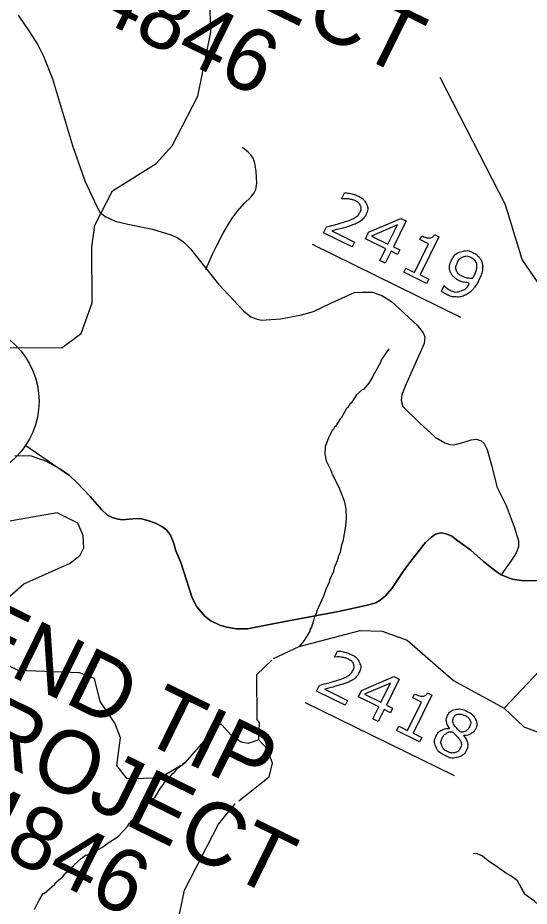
# Model space of a CAD drawing. Extents: x 1428428 to 1430511, y 857911 to 859585.
# Drawn here: x 1429106.2 to 1429187.5, y 859309.5 to 859450.7 of the extents above; entities that cross this region are included whole.
import ezdxf

# ---------------------------------------------------------------- set-up
doc = ezdxf.new("R2010")
doc.units = 0
for name, color, linetype in [('Default', 7, 'Continuous'), ('Exist Hydrographic Creek Single Shore', 7, 'Continuous'), ('Exist Hydrographic Misc Water Feature', 7, 'Continuous'), ('Exist Road Non-System Type 51', 7, 'Continuous'), ('Exist Road Secondary Type 51 Attributed', 7, 'Continuous'), ('Sheet Title CELL', 7, 'Continuous')]:
    doc.layers.add(name, color=color, linetype=linetype)

msp = doc.modelspace()

# ---------------------------------------------------------------- linework, layer by layer
at = {"layer": 'Default'}
for p, q in [((1429153.04, 859414.68), (1429176.61, 859403.09)), ((1429151.93, 859341.85), (1429175.56, 859330.22))]:
    msp.add_line(p, q, dxfattribs=at)
for points in [[(1429157.75, 859421.88), (1429157.7, 859421.9), (1429158.17, 859422.85)], [(1429159.39, 859414.24), (1429154.83, 859416.48), (1429155.3, 859417.43)], [(1429166.57, 859413.05), (1429165.57, 859413.55), (1429164.64, 859411.65), (1429163.77, 859412.08), (1429164.71, 859413.97), (1429161.48, 859415.56), (1429161.99, 859416.6), (1429167.12, 859418.79), (1429167.95, 859418.38), (1429165.93, 859414.27), (1429166.93, 859413.78), (1429166.57, 859413.05)], [(1429165.06, 859414.7), (1429166.56, 859417.74), (1429162.45, 859415.98), (1429165.06, 859414.7)], [(1429156.15, 859416.8), (1429159.77, 859415.02), (1429159.39, 859414.24)], [(1429171.2, 859408.42), (1429167.56, 859410.22), (1429167.9, 859410.9), (1429169.3, 859410.21), (1429171.52, 859414.72), (1429170.12, 859415.41), (1429170.42, 859416.03)], [(1429172.45, 859416.2), (1429173.15, 859415.85), (1429170.17, 859409.79), (1429171.54, 859409.11), (1429171.2, 859408.42)], [(1429173.55, 859407.23), (1429173.98, 859408.1), (1429174.02, 859408.08)], [(1429156.63, 859349.05), (1429156.58, 859349.07), (1429157.05, 859350.02)], [(1429165.46, 859340.22), (1429164.46, 859340.71), (1429163.52, 859338.82), (1429162.66, 859339.24), (1429163.59, 859341.14), (1429160.36, 859342.73), (1429160.87, 859343.77), (1429166, 859345.96), (1429166.83, 859345.55), (1429164.81, 859341.44), (1429165.81, 859340.95), (1429165.46, 859340.22)], [(1429158.27, 859341.4), (1429153.71, 859343.65), (1429154.18, 859344.6)], [(1429155.03, 859343.97), (1429158.65, 859342.18), (1429158.27, 859341.4)], [(1429163.94, 859341.87), (1429165.44, 859344.9), (1429161.33, 859343.15), (1429163.94, 859341.87)], [(1429170.08, 859335.59), (1429166.44, 859337.38), (1429166.78, 859338.07), (1429168.18, 859337.38), (1429170.4, 859341.89), (1429169, 859342.58), (1429169.3, 859343.19)], [(1429171.33, 859343.36), (1429172.03, 859343.02), (1429169.05, 859336.95), (1429170.42, 859336.28), (1429170.08, 859335.59)], [(1429174.84, 859337.71), (1429174.86, 859337.74)], [(1429177.08, 859336.6), (1429177.06, 859336.57)]]:
    msp.add_lwpolyline(points, dxfattribs=at)
for points in [[(1429155.3, 859417.43), (1429155.97, 859417.6), (1429156.65, 859417.78), (1429157.33, 859417.95), (1429157.94, 859418.15), (1429159.22, 859418.56), (1429159.79, 859418.89), (1429160.35, 859419.23), (1429160.63, 859419.8), (1429160.89, 859420.33), (1429160.69, 859420.79), (1429160.49, 859421.26), (1429159.87, 859421.57), (1429159.46, 859421.77), (1429158.9, 859421.86), (1429158.35, 859421.95), (1429157.75, 859421.88)], [(1429158.17, 859422.85), (1429158.57, 859422.85), (1429159.17, 859422.72), (1429159.77, 859422.58), (1429160.27, 859422.34), (1429161.31, 859421.83), (1429161.65, 859421.04), (1429161.99, 859420.25), (1429161.57, 859419.4), (1429161.38, 859419.01), (1429161.12, 859418.73), (1429160.86, 859418.45), (1429160.53, 859418.24), (1429160.21, 859418.05), (1429159.84, 859417.89), (1429159.47, 859417.74), (1429158.97, 859417.58), (1429158.25, 859417.34), (1429157.52, 859417.15), (1429156.78, 859416.96), (1429156.15, 859416.8)], [(1429170.42, 859416.03), (1429170.7, 859415.89), (1429171.05, 859415.77), (1429171.4, 859415.66), (1429171.61, 859415.67), (1429171.88, 859415.68), (1429172.08, 859415.8), (1429172.29, 859415.91), (1429172.45, 859416.2)], [(1429174.02, 859408.08), (1429174.12, 859407.95), (1429174.33, 859407.77), (1429174.54, 859407.59), (1429174.83, 859407.44), (1429175.83, 859406.95), (1429176.69, 859407.27), (1429177.55, 859407.59), (1429178.16, 859408.6), (1429177.62, 859408.55), (1429177.19, 859408.63), (1429176.77, 859408.7), (1429176.33, 859408.92), (1429175.92, 859409.12), (1429175.62, 859409.37), (1429175.32, 859409.61), (1429175.1, 859410.02), (1429174.84, 859410.49), (1429174.85, 859411.01), (1429174.86, 859411.54), (1429175.15, 859412.13), (1429175.66, 859413.16), (1429176.65, 859413.47), (1429177.65, 859413.79), (1429178.62, 859413.31), (1429179.11, 859413.07), (1429179.45, 859412.71), (1429179.8, 859412.35), (1429179.96, 859411.9), (1429180.16, 859411.33), (1429180.07, 859410.64), (1429179.99, 859409.95), (1429179.53, 859409.01)], [(1429178.71, 859409.66), (1429179.06, 859410.36), (1429179.12, 859410.86), (1429179.19, 859411.35), (1429179.05, 859411.71), (1429178.94, 859412.02), (1429178.74, 859412.23), (1429178.54, 859412.44), (1429178.25, 859412.58), (1429177.6, 859412.9), (1429177.02, 859412.67), (1429176.45, 859412.45), (1429176.09, 859411.72), (1429175.87, 859411.29), (1429175.86, 859410.96), (1429175.85, 859410.62), (1429176.04, 859410.28), (1429176.17, 859410.04), (1429176.39, 859409.87), (1429176.61, 859409.7), (1429176.91, 859409.56), (1429177.26, 859409.38), (1429177.67, 859409.3), (1429178.08, 859409.22), (1429178.48, 859409.24), (1429178.54, 859409.34), (1429178.59, 859409.43), (1429178.64, 859409.52), (1429178.71, 859409.66)], [(1429179.53, 859409.01), (1429179.1, 859408.13), (1429178.54, 859407.51), (1429177.99, 859406.89), (1429177.33, 859406.58), (1429176.67, 859406.27), (1429175.91, 859406.29), (1429175.15, 859406.32), (1429174.31, 859406.73), (1429174.08, 859406.84), (1429173.88, 859406.97), (1429173.69, 859407.1), (1429173.55, 859407.23)], [(1429157.05, 859350.02), (1429157.45, 859350.02), (1429158.05, 859349.88), (1429158.65, 859349.75), (1429159.15, 859349.5), (1429160.19, 859348.99), (1429160.53, 859348.21), (1429160.88, 859347.42), (1429160.46, 859346.56), (1429160.27, 859346.18), (1429160.01, 859345.9), (1429159.75, 859345.61), (1429159.41, 859345.41), (1429159.09, 859345.21), (1429158.72, 859345.06), (1429158.35, 859344.91), (1429157.85, 859344.74), (1429157.13, 859344.51), (1429156.4, 859344.32), (1429155.67, 859344.12), (1429155.03, 859343.97)], [(1429154.18, 859344.6), (1429154.86, 859344.77), (1429155.53, 859344.94), (1429156.21, 859345.11), (1429156.82, 859345.31), (1429158.1, 859345.72), (1429158.67, 859346.06), (1429159.23, 859346.4), (1429159.52, 859346.97), (1429159.77, 859347.49), (1429159.57, 859347.96), (1429159.37, 859348.43), (1429158.75, 859348.73), (1429158.34, 859348.94), (1429157.79, 859349.03), (1429157.23, 859349.12), (1429156.63, 859349.05)], [(1429169.3, 859343.19), (1429169.59, 859343.05), (1429169.93, 859342.94), (1429170.28, 859342.83), (1429170.5, 859342.84), (1429170.76, 859342.85), (1429170.96, 859342.96), (1429171.17, 859343.08), (1429171.33, 859343.36)], [(1429174.86, 859337.74), (1429174.46, 859338.29), (1429174.37, 859338.77), (1429174.27, 859339.24), (1429174.53, 859339.75), (1429174.9, 859340.51), (1429175.77, 859340.71), (1429176.65, 859340.91), (1429177.61, 859340.44), (1429178.62, 859339.94), (1429178.98, 859339.16), (1429179.35, 859338.38), (1429178.98, 859337.63), (1429178.75, 859337.18), (1429178.25, 859336.88), (1429177.75, 859336.58), (1429177.08, 859336.6)], [(1429178.08, 859338.06), (1429178.32, 859338.55), (1429178.09, 859339.02), (1429177.86, 859339.49), (1429177.28, 859339.77), (1429176.71, 859340.05), (1429176.21, 859339.96), (1429175.71, 859339.87), (1429175.49, 859339.41), (1429175.33, 859339.08), (1429175.39, 859338.76), (1429175.46, 859338.43), (1429175.74, 859338.06), (1429175.87, 859337.9), (1429176.12, 859337.61), (1429176.37, 859337.33), (1429176.62, 859337.09), (1429177.22, 859337.17), (1429177.55, 859337.41), (1429177.88, 859337.64), (1429178.08, 859338.06)], [(1429177.54, 859334.25), (1429177.11, 859333.38), (1429176.14, 859333.13), (1429175.18, 859332.89), (1429174.15, 859333.4), (1429173.05, 859333.94), (1429172.68, 859334.82), (1429172.31, 859335.71), (1429172.75, 859336.59), (1429173.02, 859337.15), (1429173.57, 859337.44), (1429174.12, 859337.74), (1429174.84, 859337.71)], [(1429176.57, 859334.62), (1429176.77, 859335.04), (1429176.71, 859335.38), (1429176.65, 859335.72), (1429176.24, 859336.24), (1429176.08, 859336.44), (1429175.87, 859336.65), (1429175.66, 859336.86), (1429175.31, 859337.22), (1429174.8, 859337.2), (1429174.37, 859336.94), (1429173.93, 859336.68), (1429173.7, 859336.2), (1429173.4, 859335.59), (1429173.62, 859334.99), (1429173.85, 859334.39), (1429174.49, 859334.07), (1429175.15, 859333.74), (1429175.72, 859333.89), (1429176.28, 859334.03), (1429176.57, 859334.62)], [(1429177.06, 859336.57), (1429177.56, 859335.99), (1429177.7, 859335.43), (1429177.84, 859334.87), (1429177.54, 859334.25)]]:
    msp.add_open_spline(points, degree=3, dxfattribs=at)
at = {"layer": 'Exist Hydrographic Creek Single Shore'}
for points in [[(1429102.76, 859356.39), (1429103.11, 859357.13), (1429107.2, 859360.7), (1429114.54, 859364), (1429116.13, 859365.25), (1429116.73, 859366.42), (1429116.63, 859368.39), (1429115.75, 859370.32), (1429112.48, 859372.01), (1429104.63, 859370.61), (1429096.75, 859371.35), (1429092.76, 859374.53), (1429092.24, 859375.69), (1429092.49, 859378)], [(1429146.82, 859348.8), (1429146.86, 859348.83), (1429150.95, 859350.75), (1429160.63, 859353.31), (1429164.14, 859353.2), (1429168.09, 859351.75), (1429175.46, 859345.35), (1429183.53, 859340.95)], [(1429132.07, 859331.8), (1429128.82, 859329.84), (1429123.64, 859329.69), (1429121.97, 859331.85), (1429122.53, 859336.22), (1429121.68, 859338.58), (1429119.32, 859342.02), (1429118.4, 859345.67), (1429116.03, 859346.53), (1429106.28, 859346.91), (1429103.48, 859348.37), (1429102.94, 859349.26)], [(1429183.53, 859340.95), (1429186.68, 859337.99), (1429191.07, 859336.31), (1429192.86, 859339.33), (1429194.28, 859344.66), (1429196.27, 859347.43)], [(1429142.24, 859266.66), (1429143.99, 859272.42), (1429146.47, 859273.58), (1429149.91, 859274.45), (1429150.91, 859277.12), (1429150.87, 859278.47), (1429153.46, 859282.38), (1429153.58, 859287.34), (1429152.09, 859288.85), (1429144.6, 859290.66), (1429134.41, 859291.27), (1429133.27, 859292.01), (1429131.12, 859298), (1429131.37, 859305.4), (1429132.73, 859312.02), (1429138.15, 859322.52), (1429140.73, 859325.69), (1429140.77, 859325.72)]]:
    msp.add_lwpolyline(points, dxfattribs=at)
at = {"layer": 'Exist Hydrographic Misc Water Feature'}
for points in [[(1429097.34, 859398.23), (1429113.3, 859398.27), (1429116.3, 859400.49), (1429118.07, 859405.34), (1429117.98, 859414.26), (1429118.45, 859417.71), (1429121.28, 859423.19), (1429128.2, 859427.52), (1429130.78, 859430.32), (1429134.86, 859438.19), (1429136.92, 859448.36), (1429136.23, 859470.29), (1429135.95, 859472.66)], [(1429183.53, 859340.95), (1429190.11, 859347.89), (1429192.31, 859352.15), (1429194.1, 859362.53), (1429197.05, 859371.87), (1429196.77, 859372.39), (1429197.6, 859378.75), (1429197.28, 859384.31), (1429193.91, 859398.84), (1429191.95, 859404.14), (1429186.39, 859412.27), (1429183.75, 859420.95), (1429173.37, 859441.18)], [(1429165.21, 859398.05), (1429164.06, 859396.35), (1429163.82, 859395.8), (1429162.72, 859393.84), (1429162.68, 859393.68), (1429162.01, 859392.6), (1429161.15, 859391.6), (1429161.04, 859391.57), (1429160.06, 859390.72), (1429159.22, 859389.44), (1429159.07, 859389.34), (1429158.64, 859388.67), (1429158.49, 859388.56), (1429157.61, 859387.04), (1429157.46, 859386.93), (1429156.73, 859385.69), (1429156.59, 859385.58), (1429156.37, 859385.16), (1429156.22, 859385.05), (1429155.63, 859383.92), (1429155.08, 859382.5), (1429155.02, 859381.35), (1429155.25, 859380.24), (1429155.95, 859378.89), (1429156.27, 859378.04), (1429157.25, 859376.09), (1429158.12, 859373.88), (1429158.36, 859372.68), (1429158.44, 859371.1), (1429158.29, 859369.87), (1429157.88, 859367.42), (1429157.69, 859366.89), (1429157.46, 859365.75), (1429157.16, 859365), (1429157.16, 859364.82), (1429157.05, 859364.7), (1429157.01, 859364.36), (1429156.53, 859363.26), (1429156.53, 859363.08), (1429156.34, 859362.55), (1429155.78, 859361.3), (1429155.71, 859360.98), (1429155.19, 859359.81), (1429154.81, 859358.74), (1429153.74, 859356.41), (1429153.63, 859355.93), (1429153.41, 859355.51), (1429153.25, 859354.86), (1429153.11, 859354.58), (1429153.1, 859354.4), (1429152.96, 859354.12), (1429152.95, 859353.94), (1429152.66, 859353.37), (1429152.66, 859353.19), (1429151.77, 859351.67), (1429150.95, 859350.75)], [(1429144.52, 859335.93), (1429144.63, 859338.68), (1429144.27, 859339.09), (1429144.24, 859346.27), (1429146.6, 859348.58)], [(1429144.52, 859335.93), (1429142.86, 859335.31), (1429141.75, 859335.51), (1429140.13, 859336.65), (1429138.63, 859338.37), (1429137.82, 859338.36), (1429136.16, 859336.11), (1429132.8, 859332.25), (1429132.39, 859332)], [(1429141.37, 859326.2), (1429146.17, 859330.05), (1429146.72, 859332.2), (1429145.85, 859334.5), (1429144.52, 859335.93)], [(1429108.9, 859308.96), (1429109.59, 859310.3), (1429110.29, 859311.48), (1429110.41, 859311.47), (1429112.1, 859312.97), (1429112.29, 859313.24), (1429113.44, 859314.26), (1429113.88, 859314.75), (1429114.17, 859314.96), (1429114.46, 859315.35), (1429115.12, 859315.91), (1429115.19, 859316.06), (1429116.28, 859317.02), (1429117, 859317.55), (1429117.14, 859317.57), (1429118.35, 859318.13), (1429119.59, 859318.81), (1429120.75, 859319.66), (1429120.87, 859319.67), (1429121.87, 859320.34), (1429122.27, 859320.67), (1429123.65, 859322.12), (1429124.01, 859322.65), (1429124.16, 859322.75), (1429124.31, 859323.04), (1429124.67, 859323.39), (1429124.82, 859323.67), (1429125.69, 859324.66), (1429125.98, 859324.87), (1429126.89, 859325.93), (1429128.05, 859326.77), (1429128.81, 859328.09), (1429129.4, 859328.86), (1429129.55, 859329.15), (1429130.2, 859329.89), (1429130.49, 859330.1), (1429130.79, 859330.49), (1429131.07, 859330.7), (1429131.73, 859331.44), (1429132.8, 859332.25)]]:
    msp.add_lwpolyline(points, dxfattribs=at)
at = {"layer": 'Exist Road Non-System Type 51'}
for points in [[(1429136.13, 859410.65), (1429137.18, 859413.12), (1429137.88, 859414.47), (1429138.84, 859416.32), (1429139.77, 859417.95), (1429140.34, 859418.88), (1429141.15, 859419.94), (1429142.23, 859421.15), (1429143.28, 859422.14), (1429143.79, 859422.86), (1429144.07, 859423.4), (1429144.22, 859424.4), (1429144.14, 859426.24), (1429143.92, 859427.57), (1429143.65, 859428.34), (1429143.26, 859428.9), (1429142.84, 859429.3), (1429141.92, 859430.05)], [(1429189.47, 859308.95), (1429189, 859309.7), (1429188.35, 859310.24), (1429186.92, 859311.27), (1429186.3, 859312.31), (1429185.63, 859313.47), (1429184.57, 859314.31), (1429183.76, 859314.75), (1429182.45, 859315.65), (1429180.99, 859316.7), (1429180.11, 859317.42), (1429179.27, 859317.8), (1429178.59, 859317.84)]]:
    msp.add_lwpolyline(points, dxfattribs=at)
at = {"layer": 'Exist Road Secondary Type 51 Attributed'}
for points in [[(1429106.31, 859451.07), (1429108.1, 859448.46), (1429109.41, 859446.39), (1429110.32, 859444.59), (1429111.75, 859440.97), (1429114.91, 859430.39), (1429116.9, 859424.76), (1429118.81, 859420.7), (1429119.29, 859419.79), (1429120.11, 859419.08), (1429121.73, 859418.33), (1429123.74, 859417.89), (1429127.62, 859417.08), (1429130.56, 859416.19), (1429131.57, 859415.73), (1429132.58, 859415.05), (1429133.64, 859414), (1429138.12, 859408.35), (1429142.09, 859404.07), (1429143.26, 859403.16), (1429144.13, 859402.8), (1429144.95, 859402.63), (1429148, 859402.81), (1429151.31, 859403.44), (1429153.25, 859403.98), (1429156, 859405.29), (1429158.33, 859406.36), (1429159.72, 859406.99), (1429160.93, 859407.07), (1429162.6, 859407.04), (1429164.11, 859406.52), (1429165.6, 859405.59), (1429169.71, 859401.81), (1429170.68, 859400.58), (1429170.92, 859399.94), (1429170.82, 859398.9), (1429167.86, 859392.23), (1429167.26, 859390.72), (1429167.16, 859389.91), (1429167.44, 859388.87), (1429170.03, 859386.36), (1429172.59, 859384.01), (1429174.09, 859383.09), (1429174.9, 859382.84), (1429175.59, 859382.8), (1429176.96, 859383.14), (1429178.27, 859383.58), (1429179.16, 859383.71), (1429179.85, 859383.44), (1429180.35, 859383.01), (1429180.82, 859382.06), (1429181.53, 859379.54), (1429182.41, 859375.99), (1429183.83, 859373.16), (1429185.14, 859369.74), (1429185.83, 859367.56), (1429185.81, 859366.59), (1429185.44, 859365.61), (1429184.69, 859364.48), (1429183.05, 859362.14)], [(1429180.27, 859364.26), (1429178.25, 859366.04), (1429176.18, 859367.54), (1429175.23, 859368.28), (1429174.29, 859368.66), (1429173.46, 859368.81), (1429172.62, 859368.62), (1429171.96, 859368.12), (1429171.05, 859367.25), (1429168.84, 859364.51), (1429167.67, 859362.98), (1429165.7, 859359.97), (1429164.69, 859358.81), (1429163.82, 859358.11), (1429163.16, 859357.68), (1429162.02, 859357.34), (1429157.2, 859356.33), (1429148.39, 859354.66), (1429142.76, 859353.55), (1429140.97, 859353.57), (1429139.43, 859353.8), (1429138.32, 859354.12), (1429136.93, 859354.8), (1429135.99, 859355.49), (1429134.71, 859357.02), (1429133.97, 859358.48), (1429132.16, 859364.1), (1429131.33, 859365.93), (1429131.04, 859367.11), (1429130.49, 859368.44), (1429129.85, 859369.27), (1429129.14, 859369.81), (1429128.13, 859370.35), (1429126.91, 859370.76), (1429125.67, 859371.07), (1429124.52, 859371.03), (1429122.88, 859370.9), (1429122.16, 859370.96), (1429121.24, 859371.22), (1429120.47, 859371.64), (1429119.61, 859372.47), (1429117.73, 859374.6), (1429115.64, 859376.83), (1429114.46, 859377.9), (1429112.92, 859378.96), (1429110.8, 859380.15), (1429108.4, 859380.99), (1429105.74, 859381.06)], [(1429183.05, 859362.14), (1429182.25, 859362.64), (1429180.27, 859364.26)], [(1429199.51, 859358), (1429198.55, 859358.34), (1429196.79, 859359.1), (1429195.28, 859359.62), (1429192.83, 859360.52), (1429190.8, 859361.03), (1429189.55, 859361.16), (1429186.28, 859361.23), (1429184.82, 859361.46), (1429183.05, 859362.14)]]:
    msp.add_lwpolyline(points, dxfattribs=at)
at = {"layer": 'Sheet Title CELL'}
for points in [[(1429107.34, 859382.79), (1429114.46, 859377.9), (1429115.64, 859376.83), (1429117.73, 859374.6), (1429119.61, 859372.47), (1429120.47, 859371.64), (1429121.24, 859371.22), (1429122.16, 859370.96), (1429122.88, 859370.9), (1429124.52, 859371.03), (1429125.67, 859371.07), (1429126.91, 859370.76), (1429128.13, 859370.35), (1429129.14, 859369.81), (1429129.85, 859369.27), (1429130.49, 859368.44), (1429131.04, 859367.11), (1429131.33, 859365.93), (1429132.16, 859364.1), (1429133.97, 859358.48), (1429134.71, 859357.02), (1429135.99, 859355.49), (1429136.93, 859354.8), (1429138.32, 859354.12), (1429139.43, 859353.8), (1429140.97, 859353.57), (1429142.76, 859353.55), (1429148.39, 859354.66), (1429157.2, 859356.33), (1429162.02, 859357.34), (1429163.16, 859357.68), (1429163.82, 859358.11), (1429164.69, 859358.81), (1429165.7, 859359.97), (1429167.67, 859362.98), (1429168.84, 859364.51), (1429171.05, 859367.25), (1429171.96, 859368.12), (1429172.62, 859368.62), (1429173.46, 859368.81), (1429174.29, 859368.66), (1429175.23, 859368.28), (1429176.18, 859367.54), (1429178.25, 859366.04), (1429180.27, 859364.26)], [(1429180.27, 859364.26), (1429182.25, 859362.64), (1429183.05, 859362.14)], [(1429183.05, 859362.14), (1429184.82, 859361.46), (1429186.28, 859361.23), (1429189.55, 859361.16), (1429190.8, 859361.03), (1429192.83, 859360.52), (1429195.28, 859359.62), (1429196.79, 859359.1), (1429198.55, 859358.34), (1429199.51, 859358)]]:
    msp.add_lwpolyline(points, dxfattribs=at)
msp.add_circle((1429097.08, 859389.7), 12.53, dxfattribs=at)

# ---------------------------------------------------------------- texts
at = {"layer": 'Default'}
for s, p in [('PROJECT', (1429111.43, 859468.8)), ('B-4846', (1429105.64, 859457.03)), ('END TIP', (1429096.7, 859350.15)), ('PROJECT', (1429090.91, 859338.39)), ('B-4846', (1429085.12, 859326.62))]:
    msp.add_text(s, height=10, rotation=333.8001, dxfattribs=at).set_placement(p)

doc.saveas('drawing.dxf')
